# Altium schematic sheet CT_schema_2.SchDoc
size 365 x 192 mm
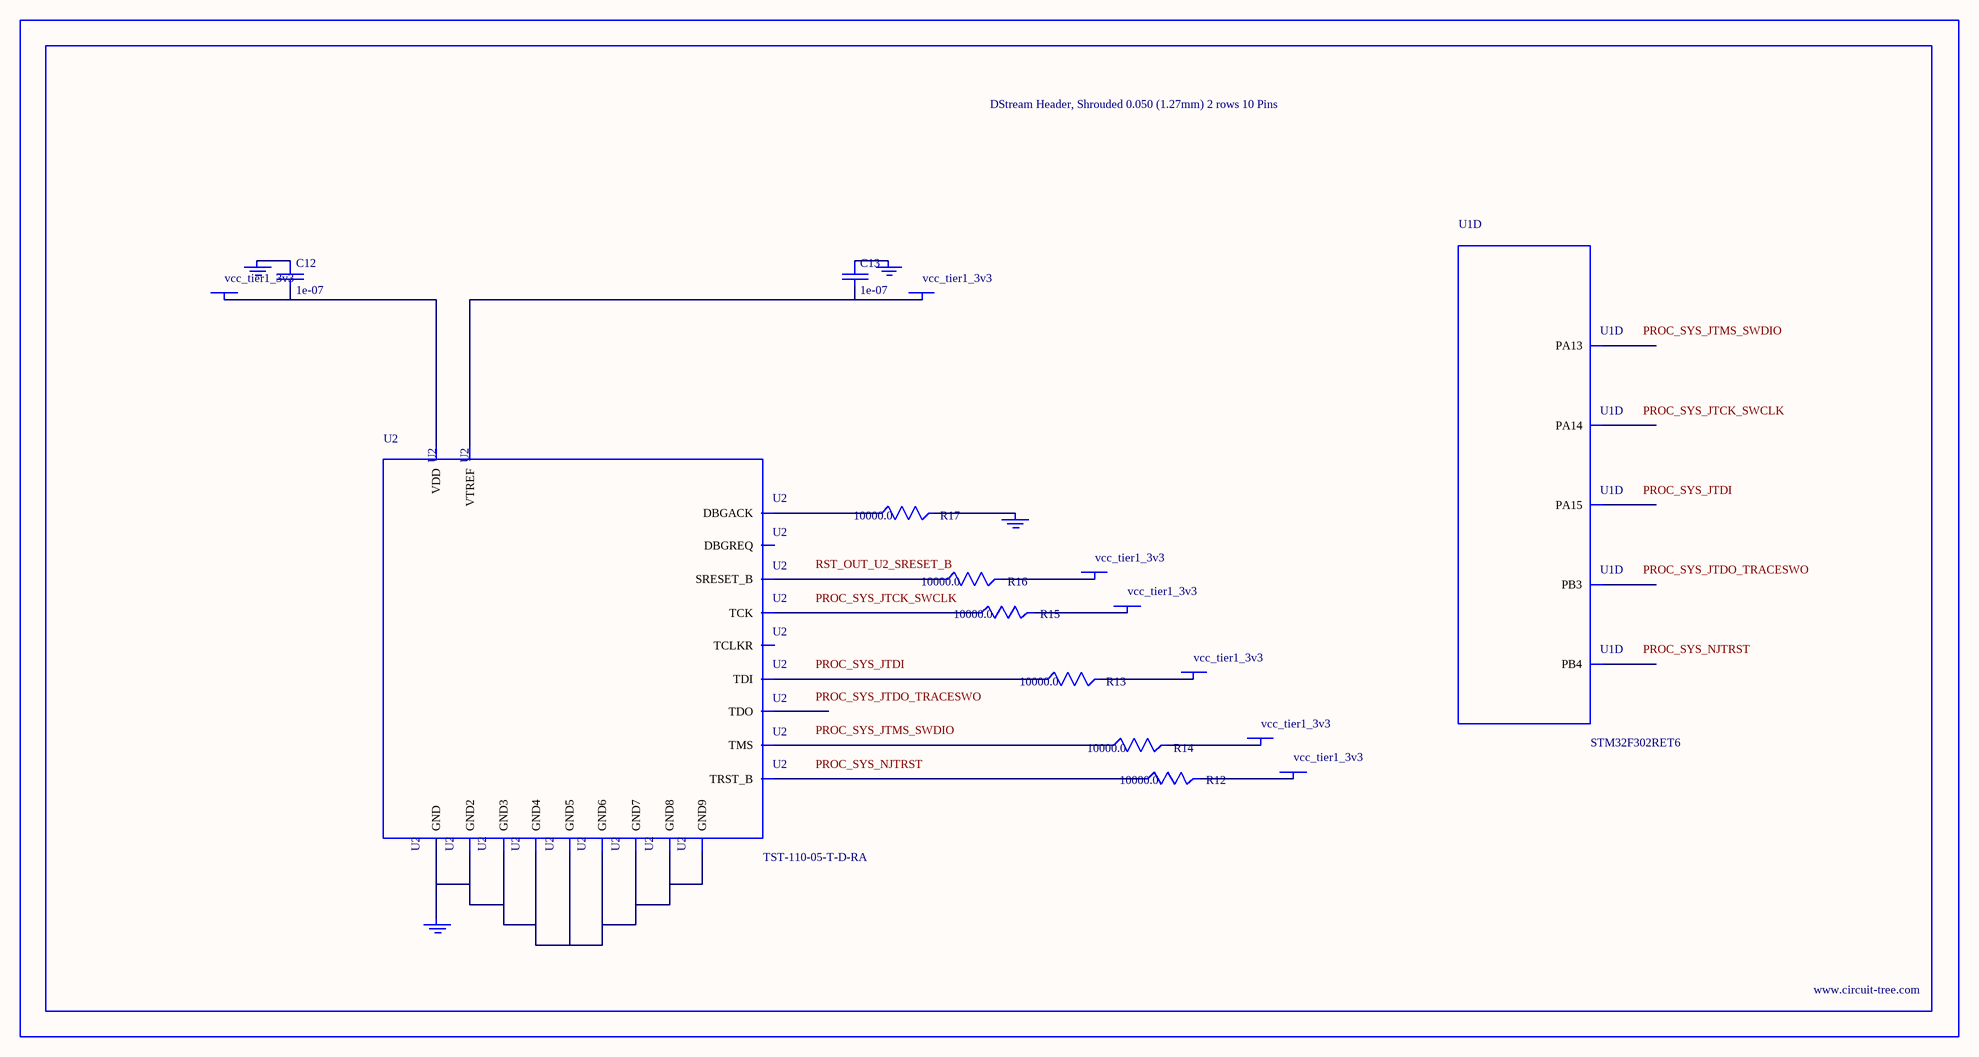
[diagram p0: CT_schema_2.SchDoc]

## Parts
BORDER1  (no value)
C12  1e-07  [C0402]
C13  1e-07  [C0402]
GND_INSTANCE_1_0  (no value)
GND_INSTANCE_1_1  (no value)
GND_INSTANCE_1_2  (no value)
GND_INSTANCE_1_3  (no value)
POWER_INSTANCE_1_0  vcc_tier1_3v3
POWER_INSTANCE_1_1  vcc_tier1_3v3
POWER_INSTANCE_1_2  vcc_tier1_3v3
POWER_INSTANCE_1_3  vcc_tier1_3v3
POWER_INSTANCE_1_4  vcc_tier1_3v3
POWER_INSTANCE_1_5  vcc_tier1_3v3
POWER_INSTANCE_1_6  vcc_tier1_3v3
R12  10000.0  [R0603]
R13  10000.0  [R0603]
R14  10000.0  [R0603]
R15  10000.0  [R0603]
R16  10000.0  [R0603]
R17  10000.0  [R0603]
U1  STM32F302RET6  [LQFP64]  (part D of 7)
U2  TST-110-05-T-D-RA  [TST-110-05-T-D-RA]

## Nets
NetC12_1: C12.1 GND_INSTANCE_1_1.0(GND)
NetC12_2: C12.2 POWER_INSTANCE_1_1.0(PWR) U2.2(VDD)
NetC13_1: C13.1 GND_INSTANCE_1_0.0(GND)
NetC13_2: C13.2 POWER_INSTANCE_1_0.0(PWR) U2.1(VTREF)
NetGND_INSTANCE_1_2_0: GND_INSTANCE_1_2.0(GND) R17.2
NetGND_INSTANCE_1_3_0: GND_INSTANCE_1_3.0(GND) U2.4(GND) U2.6(GND2) U2.8(GND3) U2.10(GND4) U2.12(GND5) U2.14(GND6) U2.16(GND7) U2.18(GND8) U2.20(GND9)
NetPOWER_INSTANCE_1_2_0: POWER_INSTANCE_1_2.0(PWR) R12.2
NetPOWER_INSTANCE_1_3_0: POWER_INSTANCE_1_3.0(PWR) R13.2
NetPOWER_INSTANCE_1_4_0: POWER_INSTANCE_1_4.0(PWR) R14.2
NetPOWER_INSTANCE_1_5_0: POWER_INSTANCE_1_5.0(PWR) R15.2
NetPOWER_INSTANCE_1_6_0: POWER_INSTANCE_1_6.0(PWR) R16.2
NetR12_1: R12.1 U2.3(TRST_B)
NetR13_1: R13.1 U2.5(TDI)
NetR14_1: R14.1 U2.7(TMS)
NetR15_1: R15.1 U2.9(TCK)
NetR16_1: R16.1 U2.15(SRESET_B)
NetR17_1: R17.1 U2.19(DBGACK)

Not connected (* = marked no-connect by the designer): U1 46(PA13) 49(PA14) 50(PA15) 55(PB3) 56(PB4); U2 11(TCLKR) 13(TDO) 17(DBGREQ)

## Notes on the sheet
- Labels drawn without touching a wire or pin: PROC_SYS_JTCK_SWCLK, PROC_SYS_JTDI, PROC_SYS_JTDO_TRACESWO, PROC_SYS_JTMS_SWDIO, PROC_SYS_NJTRST, RST_OUT_U2_SRESET_B

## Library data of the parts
BORDER1 = BORDER_PAGE1
C12 C13 = C0402C104K3RACTU
GND_INSTANCE_1_0-GND_INSTANCE_1_3 = GND
POWER_INSTANCE_1_0-POWER_INSTANCE_1_6 = PWR
R12-R17 = RC0603JR-0710KL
